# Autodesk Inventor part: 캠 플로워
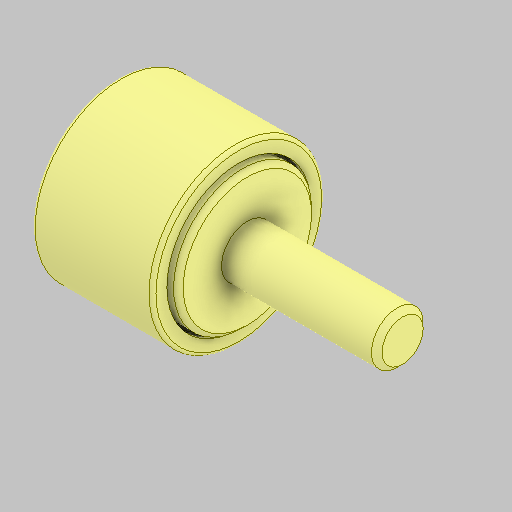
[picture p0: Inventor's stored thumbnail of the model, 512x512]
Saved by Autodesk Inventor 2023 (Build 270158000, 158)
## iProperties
Created: 2025-09
Part Number: 캠 플로워
Material: 일반
Description: Cam Follower with a Hexagon Socket Model CF-A-
Document SubType Name: Modeling
Designer: home
Density: 1 g/cm^3
Appearance: 기본값
Company: THK
Author: jhkim
Sending System: Autodesk Inventor 2026
Preprocessor: ST-DEVELOPER v20.1
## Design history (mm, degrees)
feature "Solid1"
node "솔리드1"
